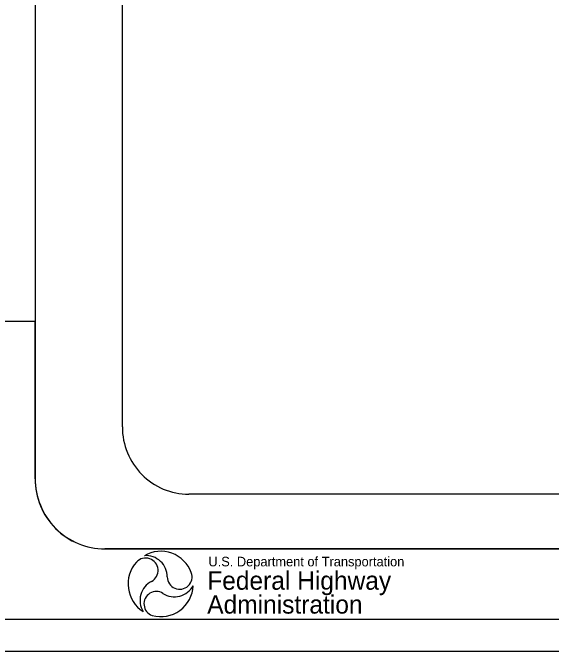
# Model space of a CAD drawing. Extents: x -1064 to 1826, y -89 to 1039.
# Drawn here: x 271.7 to 504.1, y -60.6 to 214.8 of the extents above; entities that cross this region are included whole.
import ezdxf

# ---------------------------------------------------------------- set-up
doc = ezdxf.new("R2010")
doc.units = 0
for name, color, linetype in [('PIM_COLOR_LIGHT_GRAY', 7, 'Continuous'), ('PIM_COLOR_SCDOT_TRUE_BLUE', 7, 'Continuous'), ('PIM_GENERAL_2', 7, 'Continuous'), ('PIM_LAYOUT_SPACERS', 7, 'Continuous')]:
    doc.layers.add(name, color=color, linetype=linetype)

msp = doc.modelspace()

# ---------------------------------------------------------------- linework, layer by layer
at = {"layer": 'PIM_COLOR_LIGHT_GRAY'}
for p, q in [((281.36, 898.32), (281.36, 14.03)), ((319.04, 36.14), (319.04, 876.21)), ((1722.14, 7.17), (347.67, 7.17)), ((311.5, -16.46), (1758.31, -16.46))]:
    msp.add_line(p, q, dxfattribs=at)
for centre, major_axis in [((347.67, 36.14), (0, 28.97)), ((311.5, 14.03), (0, 30.49))]:
    msp.add_ellipse(centre, major_axis=major_axis, ratio=0.988481, start_param=1.570796, end_param=3.141593, dxfattribs=at)
at = {"layer": 'PIM_COLOR_SCDOT_TRUE_BLUE'}
for p, q in [((1470.32, -16.46), (311.5, -16.46)), ((100.53, -46.67), (1460.74, -46.67))]:
    msp.add_line(p, q, dxfattribs=at)
msp.add_lwpolyline([(281.36, 13.75), (281.36, 81.64), (40.25, 81.64)], dxfattribs=at)
msp.add_ellipse((311.5, 13.75), major_axis=(0, 30.21), ratio=0.997778, start_param=1.570796, end_param=3.141593, dxfattribs=at)
at = {"layer": 'PIM_GENERAL_2'}
msp.add_lwpolyline([(325.17, -22.12), (325.15, -22.11)], dxfattribs=at)
for centre, radius, start, end in [((335.59, -31.56), 14.09, 20.4028, 119.9654), ((329.13, -25.71), 5.34, 297.7335, 137.8695), ((329.2, -28.58), 9.25, 0.2668, 94.0107), ((335.59, -31.56), 14.09, 137.8517, 237.5385), ((343.79, -28.51), 5.34, 180.2668, 20.4029), ((335.91, -38.62), 9.25, 117.7335, 211.4774), ((335.59, -31.56), 14.09, 254.932, 356.9781), ((341.56, -27.84), 9.25, 237.3786, 331.1225), ((333.7, -40.12), 5.34, 57.3786, 250.6458)]:
    msp.add_arc(centre, radius, start, end, dxfattribs=at)
at = {"layer": 'PIM_LAYOUT_SPACERS'}
msp.add_lwpolyline([(26.25, -60.57), (1826.25, -60.57), (1826.25, 1039.43), (26.25, 1039.43)], close=True, dxfattribs=at)

# ---------------------------------------------------------------- texts
at = {"layer": 'PIM_GENERAL_2'}
for s, height, p in [('U.S. Department of Transportation', 4.1374, (356.18, -23.97)), ('Federal Highway', 7.9129, (355.67, -34.04)), ('Administration', 7.9129, (355.67, -44.34))]:
    msp.add_text(s, height=height, rotation=360, dxfattribs=at).set_placement(p)

doc.saveas('drawing.dxf')
